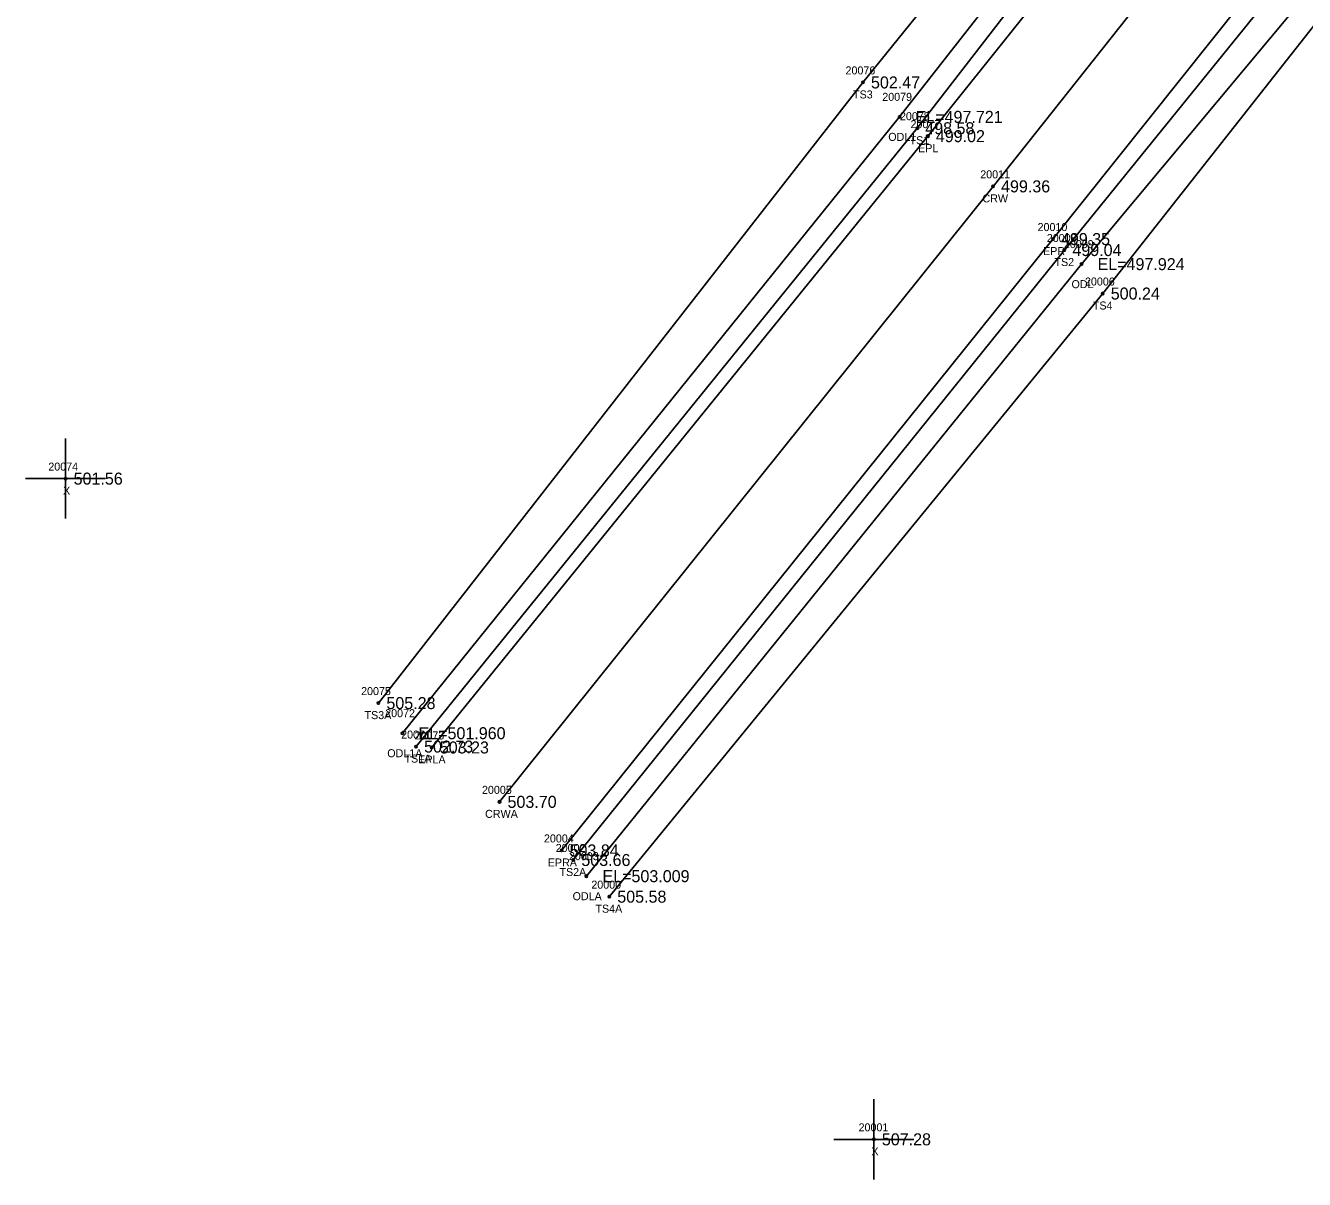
# Model space of a CAD drawing. Extents: x 1789565 to 1790548, y 909019 to 910194.
# Drawn here: x 1789565.3 to 1789725, y 909019.1 to 909163.2 of the extents above; entities that cross this region are included whole.
import ezdxf

# ---------------------------------------------------------------- set-up
doc = ezdxf.new("R2010")
doc.units = 0
for name, color, linetype in [('RD_DTM_BkLn1', 7, 'Continuous'), ('RD_DTM_BkLn2', 7, 'Continuous'), ('RD_DTM_BkLn_txCode', 7, 'Continuous'), ('RD_EX_H2O', 7, 'Continuous'), ('RD_EX_H2O_txCode', 7, 'Continuous'), ('RD_EX_Misc', 7, 'Continuous'), ('RD_EX_Misc_txCode', 7, 'Continuous'), ('RD_EX_Road', 7, 'Continuous'), ('RD_EX_Road_txCode', 7, 'Continuous'), ('RD_EX_TX_H2O_ELEV', 7, 'Continuous'), ('RD_EX_TX_Misc_ELEV', 7, 'Continuous'), ('RD_EX_TX_Road_ELEV', 7, 'Continuous'), ('RD_HC_Survey_ELEV', 7, 'Continuous'), ('RD_HC_Survey_txCode', 7, 'Continuous'), ('RD_SMD_Locator', 7, 'Continuous')]:
    doc.layers.add(name, color=color, linetype=linetype)

msp = doc.modelspace()

# ---------------------------------------------------------------- linework, layer by layer
at = {"layer": 'RD_DTM_BkLn1'}
msp.add_lwpolyline([(1789624.5, 909066.24), (1789686.15, 909143.09), (1789745.11, 909217.37), (1789803.6, 909290.4), (1789864.63, 909366.97), (1789927.82, 909445.41), (1789987.57, 909520.69), (1790044.94, 909592.68)], dxfattribs=at)
at = {"layer": 'RD_DTM_BkLn2'}
for points in [[(1789614.08, 909073.14), (1789676.68, 909150.35), (1789735.2, 909226.02), (1789793.81, 909297.32), (1789853.39, 909374.42), (1789917.15, 909454.46), (1789977.25, 909529.33), (1790025.37, 909589.9), (1790030.46, 909600.52), (1790034.43, 909600.71)], [(1789609.37, 909078.57), (1789669.9, 909156.07), (1789730.1, 909230.49), (1789787.39, 909303.09), (1789833.49, 909359.71), (1789838.38, 909362.25)], [(1789633.72, 909058.98), (1789695.06, 909135.14), (1789755.1, 909209.21), (1789813.73, 909282.9), (1789852.08, 909326.88), (1789859.67, 909329.95), (1789891.2, 909324.8)], [(1789638.21, 909054.4), (1789699.85, 909129.71), (1789733.31, 909172.18), (1789761.89, 909201.9), (1789823.56, 909274.73), (1789856.38, 909320.73), (1789862.75, 909322.59), (1789888.72, 909318.3)]]:
    msp.add_lwpolyline(points, dxfattribs=at)
at = {"layer": 'RD_EX_H2O'}
for points in [[(1789612.38, 909074.81), (1789674.47, 909151.77), (1789733.61, 909227.27), (1789792.01, 909298.88), (1789838.38, 909362.25)], [(1789635.36, 909056.96), (1789697.2, 909133.38), (1789758.1, 909206.33), (1789818.22, 909280.06), (1789854.18, 909324.3), (1789860.54, 909326.82), (1789889.88, 909320.33)]]:
    msp.add_lwpolyline(points, dxfattribs=at)
at = {"layer": 'RD_EX_Misc'}
for p, q in [((1789570.3, 909101.6), (1789570.3, 909111.6)), ((1789565.3, 909106.6), (1789575.3, 909106.6)), ((1789671.26, 909019.1), (1789671.26, 909029.1)), ((1789666.26, 909024.1), (1789676.26, 909024.1))]:
    msp.add_line(p, q, dxfattribs=at)
at = {"layer": 'RD_EX_Road'}
for points in [[(1789616.04, 909073.03), (1789678, 909149.36), (1789737.65, 909223.89), (1789795.32, 909296.33), (1789856.01, 909372.29), (1789919.82, 909451.94), (1789979.86, 909527.13), (1790037.32, 909598.58), (1790044.94, 909592.68)], [(1789632.25, 909060.17), (1789693.63, 909136.51), (1789752.94, 909210.84), (1789811.79, 909284.47), (1789846.6, 909328.43), (1789872.88, 909361.39), (1789936.05, 909439.58), (1789995.85, 909514.58), (1790052.72, 909586.51), (1790044.94, 909592.68)]]:
    msp.add_lwpolyline(points, dxfattribs=at)
at = {"layer": 'RD_SMD_Locator'}
for centre in [(1789669.9, 909156.07), (1789674.47, 909151.77), (1789676.68, 909150.35), (1789678, 909149.36), (1789686.15, 909143.09), (1789693.63, 909136.51), (1789695.06, 909135.14), (1789697.2, 909133.38), (1789699.85, 909129.71), (1789570.3, 909106.6), (1789609.37, 909078.57), (1789612.38, 909074.81), (1789614.08, 909073.14), (1789616.04, 909073.03), (1789624.5, 909066.24), (1789632.25, 909060.17), (1789633.72, 909058.98), (1789635.36, 909056.96), (1789638.21, 909054.4), (1789671.26, 909024.1)]:
    msp.add_circle(centre, 0.15, dxfattribs=at)

# ---------------------------------------------------------------- texts
at = {"layer": 'RD_DTM_BkLn_txCode'}
for s, p in [('20076', (1789667.72, 909157.07)), ('TS3', (1789668.66, 909154.07)), ('20078', (1789674.52, 909151.35)), ('TS1', (1789675.72, 909148.35)), ('20008', (1789692.86, 909136.14)), ('TS2', (1789693.82, 909133.14)), ('20006', (1789697.63, 909130.71)), ('TS4', (1789698.61, 909127.71)), ('20075', (1789607.21, 909079.57)), ('TS3A', (1789607.64, 909076.57)), ('20071', (1789612.21, 909074.14)), ('TS1A', (1789612.63, 909071.14)), ('20002', (1789631.52, 909059.98)), ('TS2A', (1789631.99, 909056.98)), ('20000', (1789635.97, 909055.4)), ('TS4A', (1789636.48, 909052.4))]:
    msp.add_text(s, height=1, dxfattribs=at).set_placement(p)
at = {"layer": 'RD_EX_H2O_txCode'}
for s, p in [('20079', (1789672.31, 909153.77)), ('ODL1', (1789673.06, 909148.77)), ('20009', (1789695, 909135.38)), ('ODL', (1789695.95, 909130.38)), ('20072', (1789610.22, 909076.81)), ('ODL1A', (1789610.48, 909071.81)), ('20003', (1789633.17, 909058.96)), ('ODLA', (1789633.63, 909053.96))]:
    msp.add_text(s, height=1, dxfattribs=at).set_placement(p)
at = {"layer": 'RD_EX_Misc_txCode'}
for s, p in [('20074', (1789568.14, 909107.6)), ('X', (1789569.98, 909104.6)), ('20001', (1789669.35, 909025.1)), ('X', (1789670.95, 909022.1))]:
    msp.add_text(s, height=1, dxfattribs=at).set_placement(p)
at = {"layer": 'RD_EX_Road_txCode'}
for s, p in [('20077', (1789675.84, 909150.36)), ('EPL', (1789676.79, 909147.36)), ('20010', (1789691.71, 909137.51)), ('EPR', (1789692.4, 909134.51)), ('20073', (1789613.88, 909074.03)), ('EPLA', (1789614.35, 909071.03)), ('20004', (1789630.05, 909061.17)), ('EPRA', (1789630.53, 909058.17))]:
    msp.add_text(s, height=1, dxfattribs=at).set_placement(p)
at = {"layer": 'RD_EX_TX_H2O_ELEV'}
for s, p in [('EL=497.721', (1789676.47, 909151.02)), ('EL=497.924', (1789699.2, 909132.63)), ('EL=501.960', (1789614.38, 909074.06)), ('EL=503.009', (1789637.36, 909056.21))]:
    msp.add_text(s, height=1.5, dxfattribs=at).set_placement(p)
at = {"layer": 'RD_EX_TX_Misc_ELEV'}
for s, p in [('502.47', (1789670.9, 909155.32)), ('498.58', (1789677.68, 909149.6)), ('499.04', (1789696.06, 909134.39)), ('500.24', (1789700.85, 909128.96)), ('501.56', (1789571.3, 909105.85)), ('505.28', (1789610.37, 909077.82)), ('502.73', (1789615.08, 909072.39)), ('503.66', (1789634.72, 909058.23)), ('505.58', (1789639.21, 909053.65)), ('507.28', (1789672.26, 909023.35))]:
    msp.add_text(s, height=1.5, dxfattribs=at).set_placement(p)
at = {"layer": 'RD_EX_TX_Road_ELEV'}
for s, p in [('499.02', (1789679, 909148.61)), ('499.35', (1789694.63, 909135.76)), ('503.23', (1789617.04, 909072.28)), ('503.84', (1789633.25, 909059.42))]:
    msp.add_text(s, height=1.5, dxfattribs=at).set_placement(p)
at = {"layer": 'RD_HC_Survey_ELEV'}
for s, p in [('499.36', (1789687.15, 909142.34)), ('503.70', (1789625.5, 909065.49))]:
    msp.add_text(s, height=1.5, dxfattribs=at).set_placement(p)
at = {"layer": 'RD_HC_Survey_txCode'}
for s, p in [('20011', (1789684.55, 909144.09)), ('CRW', (1789684.83, 909141.09)), ('20005', (1789622.31, 909067.24)), ('CRWA', (1789622.7, 909064.24))]:
    msp.add_text(s, height=1, dxfattribs=at).set_placement(p)

doc.saveas('drawing.dxf')
